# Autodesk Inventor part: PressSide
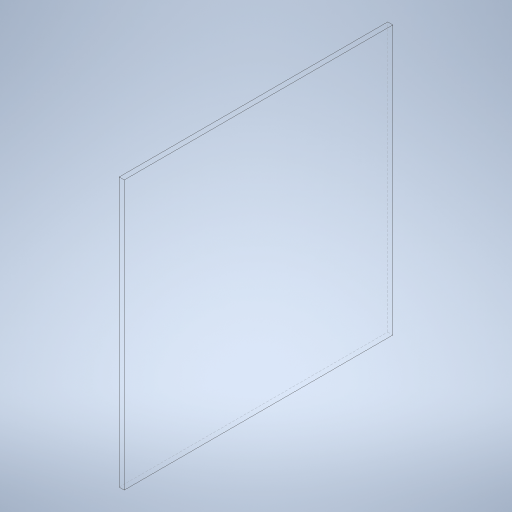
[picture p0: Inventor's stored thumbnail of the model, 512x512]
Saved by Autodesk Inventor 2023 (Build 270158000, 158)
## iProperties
Created: 2023-11
Part Number: PressSide
Material: Generic
Document SubType Name: Modeling
Designer: tornqvih
Density: 1 g/cm^3
Appearance: Default
Author: tornqvih
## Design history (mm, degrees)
sketch "Sketch1"
  geometry: L1 (0, 0)-(-105, 0); L2 (-105, 0)-(-105, -105); L3 (-105, -105)-(0, -105); L4 (0, -105)-(0, 0)
  constraints: 8 end point, 2 parallel, 1 horizontal, 1 perpendicular
  dimensions: "d0" = 105 distance of L3.end L1.start; "d1" = 105 distance of L1.start L1.end
extrude "Extrusion1" new body sketch "Sketch1" distance "d2" = 2; taper "d3" = 0 deg
body "Solid1"
